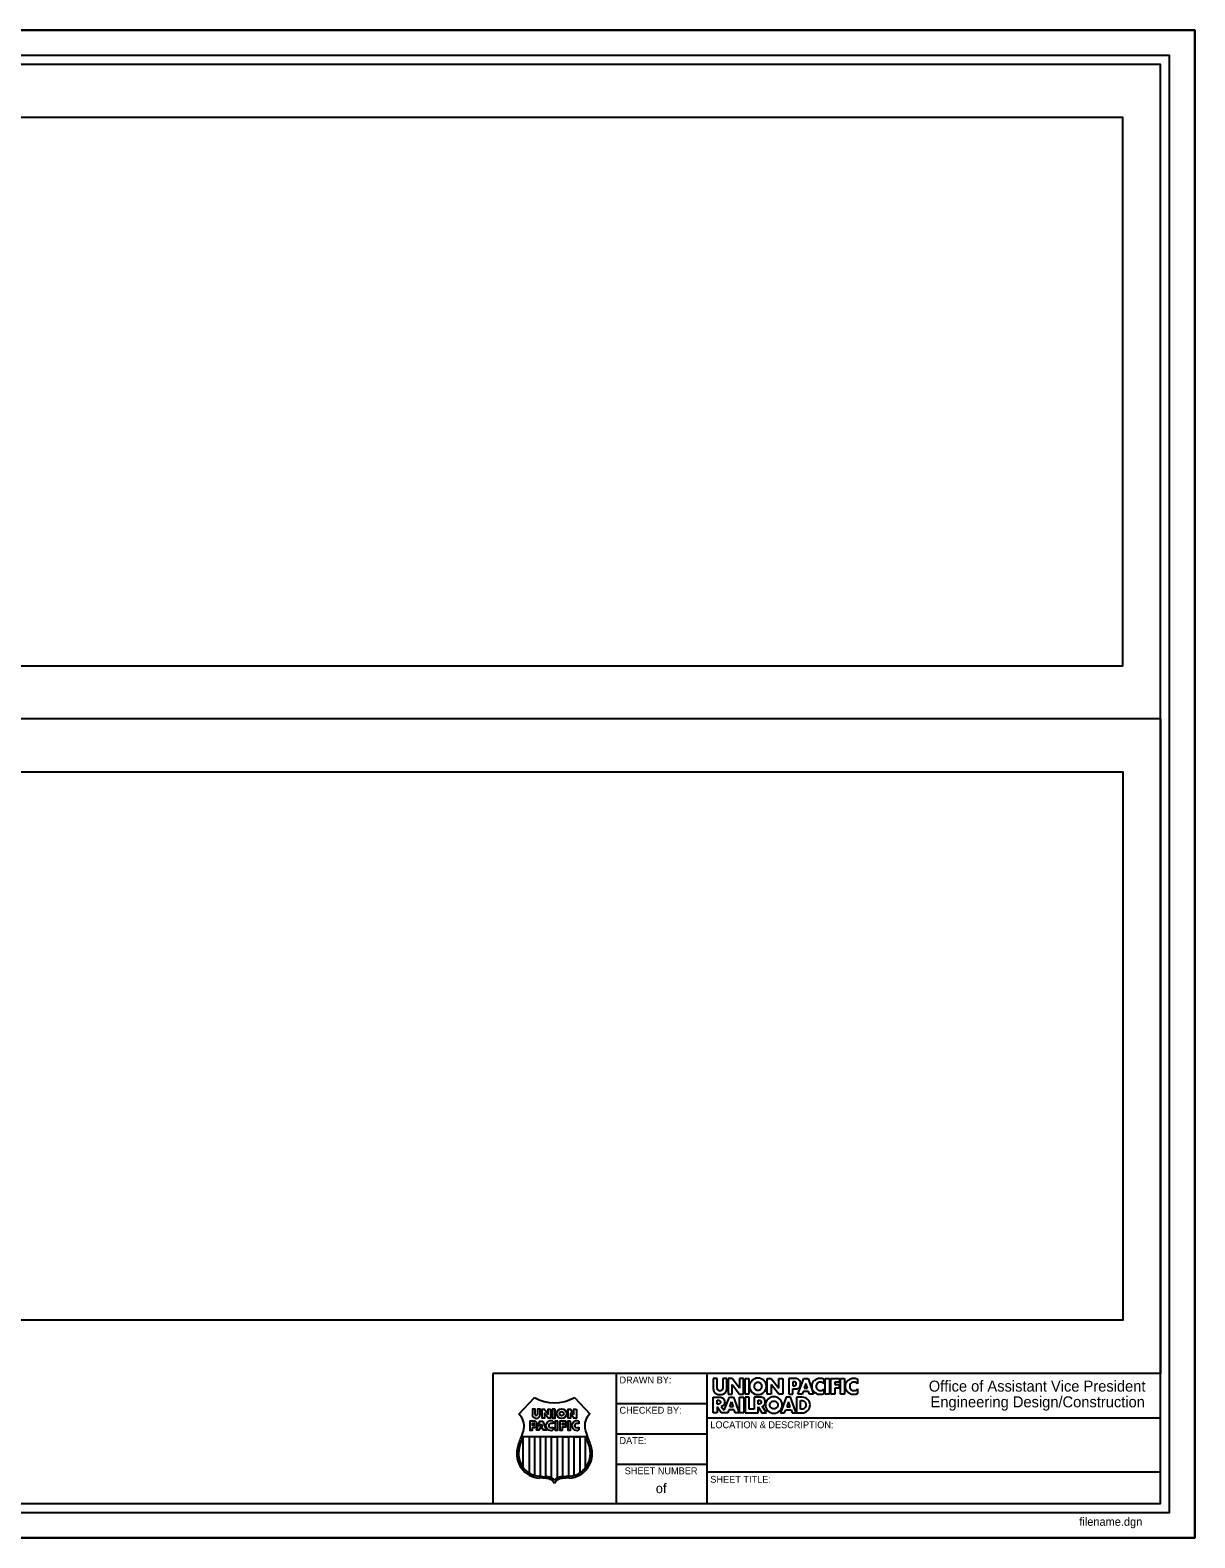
# Model space of a CAD drawing. Extents: x 0 to 17, y 0 to 11.
# Drawn here: x 8.5 to 17, y 0 to 11 of the extents above; entities that cross this region are included whole.
import ezdxf

# ---------------------------------------------------------------- set-up
doc = ezdxf.new("R2010")
doc.units = 0
for name, color, linetype in [('C-ANNO-NPLT', 7, 'Continuous'), ('Default', 7, 'Continuous'), ('G-ANNO-TTLB-TRIM', 7, 'Continuous'), ('G-BORDER', 7, 'Continuous')]:
    doc.layers.add(name, color=color, linetype=linetype)

msp = doc.modelspace()

# ---------------------------------------------------------------- linework, layer by layer
at = {"layer": 'C-ANNO-NPLT'}
for points in [[(0.975, 6.363), (16.475, 6.363), (16.475, 10.363), (0.975, 10.363)], [(0.975, 5.588), (16.475, 5.588), (16.475, 1.588), (0.975, 1.588)]]:
    msp.add_lwpolyline(points, close=True, dxfattribs=at)
at = {"layer": 'Default'}
for q in [(16.75, 10.75), (16.75, 1.2)]:
    msp.add_line((16.75, 5.975), q, dxfattribs=at)
at = {"layer": 'G-ANNO-TTLB-TRIM'}
msp.add_lwpolyline([(0, 0), (17, 0), (17, 11), (0, 11)], close=True, dxfattribs=at)
at = {"layer": 'G-BORDER'}
for p, q in [((16.75, 5.975), (0.7, 5.975)), ((16.75, 1.2), (11.876, 1.2)), ((11.876, 1.2), (11.876, 0.25)), ((12.776, 1.2), (12.776, 0.25)), ((13.439, 1.2), (13.439, 0.25)), ((13.515, 1.163), (13.485, 1.163)), ((13.485, 1.163), (13.485, 1.098)), ((13.515, 1.102), (13.515, 1.163)), ((13.584, 1.163), (13.555, 1.163)), ((13.555, 1.163), (13.555, 1.102)), ((13.584, 1.098), (13.584, 1.163)), ((13.623, 1.163), (13.593, 1.163)), ((13.593, 1.163), (13.593, 1.048)), ((13.677, 1.093), (13.623, 1.163)), ((13.623, 1.048), (13.623, 1.118)), ((13.623, 1.118), (13.623, 1.118)), ((13.623, 1.118), (13.677, 1.048)), ((13.707, 1.163), (13.677, 1.163)), ((13.677, 1.163), (13.677, 1.093)), ((13.707, 1.048), (13.707, 1.163)), ((13.717, 1.163), (13.746, 1.163)), ((13.717, 1.048), (13.717, 1.163)), ((13.746, 1.163), (13.746, 1.048)), ((13.879, 1.048), (13.879, 1.163)), ((13.879, 1.163), (13.909, 1.163)), ((13.909, 1.163), (13.963, 1.093)), ((13.963, 1.048), (13.909, 1.118)), ((13.909, 1.118), (13.909, 1.118)), ((13.909, 1.118), (13.909, 1.048)), ((13.963, 1.093), (13.963, 1.163)), ((13.963, 1.163), (13.993, 1.163)), ((13.993, 1.163), (13.993, 1.048)), ((14.081, 1.163), (14.036, 1.163)), ((14.036, 1.163), (14.036, 1.048)), ((14.07, 1.138), (14.065, 1.138)), ((14.065, 1.138), (14.065, 1.11)), ((14.065, 1.11), (14.07, 1.11)), ((14.103, 1.048), (14.146, 1.163)), ((14.146, 1.163), (14.177, 1.163)), ((14.161, 1.127), (14.149, 1.091)), ((14.173, 1.091), (14.161, 1.127)), ((14.177, 1.163), (14.218, 1.048)), ((14.293, 1.16), (14.293, 1.124)), ((14.303, 1.048), (14.303, 1.163)), ((14.303, 1.163), (14.333, 1.163)), ((14.333, 1.163), (14.333, 1.048)), ((14.343, 1.048), (14.343, 1.163)), ((14.343, 1.163), (14.407, 1.163)), ((14.407, 1.137), (14.373, 1.137)), ((14.373, 1.137), (14.373, 1.118)), ((14.373, 1.118), (14.403, 1.118)), ((14.403, 1.118), (14.403, 1.093)), ((14.407, 1.163), (14.407, 1.137)), ((14.413, 1.048), (14.413, 1.163)), ((14.413, 1.163), (14.443, 1.163)), ((14.443, 1.163), (14.443, 1.048)), ((14.537, 1.16), (14.537, 1.124)), ((12.066, 0.903), (12.18, 1.025)), ((12.18, 1.025), (12.18, 1.025)), ((12.472, 1.025), (12.586, 0.903)), ((13.485, 1.027), (13.53, 1.027)), ((13.485, 0.913), (13.485, 1.027)), ((13.515, 0.976), (13.515, 1.004)), ((13.515, 1.004), (13.518, 1.004)), ((13.566, 0.931), (13.603, 1.027)), ((13.593, 1.048), (13.623, 1.048)), ((13.603, 1.027), (13.633, 1.027)), ((13.606, 0.956), (13.618, 0.992)), ((13.618, 0.992), (13.63, 0.956)), ((13.633, 1.027), (13.674, 0.913)), ((13.677, 1.093), (13.677, 1.093)), ((13.677, 1.048), (13.707, 1.048)), ((13.678, 0.913), (13.678, 1.027)), ((13.678, 1.027), (13.708, 1.027)), ((13.708, 1.027), (13.708, 0.913)), ((13.746, 1.048), (13.717, 1.048)), ((13.718, 1.027), (13.718, 0.913)), ((13.747, 1.027), (13.718, 1.027)), ((13.747, 0.938), (13.747, 1.027)), ((13.828, 1.027), (13.784, 1.027)), ((13.784, 1.027), (13.784, 0.938)), ((13.813, 0.976), (13.813, 1.004)), ((13.813, 1.004), (13.816, 1.004)), ((13.909, 1.048), (13.879, 1.048)), ((13.963, 1.093), (13.963, 1.093)), ((13.993, 1.048), (13.963, 1.048)), ((14.018, 1.027), (13.976, 0.913)), ((14.05, 1.027), (14.018, 1.027)), ((14.034, 0.992), (14.022, 0.955)), ((14.046, 0.955), (14.034, 0.992)), ((14.036, 1.048), (14.065, 1.048)), ((14.091, 0.913), (14.05, 1.027)), ((14.065, 1.086), (14.082, 1.086)), ((14.065, 1.048), (14.065, 1.086)), ((14.135, 1.027), (14.093, 1.027)), ((14.093, 1.027), (14.093, 0.913)), ((14.133, 1.048), (14.103, 1.048)), ((14.122, 0.938), (14.122, 1.002)), ((14.122, 1.002), (14.129, 1.002)), ((14.141, 1.068), (14.133, 1.048)), ((14.181, 1.068), (14.141, 1.068)), ((14.149, 1.091), (14.173, 1.091)), ((14.188, 1.048), (14.181, 1.068)), ((14.218, 1.048), (14.188, 1.048)), ((14.293, 1.086), (14.293, 1.051)), ((14.333, 1.048), (14.303, 1.048)), ((14.373, 1.048), (14.343, 1.048)), ((14.403, 1.093), (14.373, 1.093)), ((14.373, 1.093), (14.373, 1.048)), ((14.443, 1.048), (14.413, 1.048)), ((14.537, 1.086), (14.537, 1.051)), ((12.776, 0.979), (13.439, 0.979)), ((13.515, 0.913), (13.485, 0.913)), ((13.518, 0.976), (13.515, 0.976)), ((13.543, 0.913), (13.515, 0.956)), ((13.515, 0.956), (13.515, 0.913)), ((13.591, 0.913), (13.543, 0.913)), ((13.544, 0.959), (13.566, 0.931)), ((13.598, 0.933), (13.591, 0.913)), ((13.637, 0.933), (13.598, 0.933)), ((13.63, 0.956), (13.606, 0.956)), ((13.644, 0.913), (13.637, 0.933)), ((13.674, 0.913), (13.644, 0.913)), ((13.708, 0.913), (13.678, 0.913)), ((13.718, 0.913), (13.813, 0.913)), ((13.784, 0.938), (13.747, 0.938)), ((13.816, 0.976), (13.813, 0.976)), ((13.813, 0.913), (13.813, 0.956)), ((13.813, 0.956), (13.839, 0.913)), ((13.839, 0.913), (13.875, 0.913)), ((13.875, 0.913), (13.843, 0.96)), ((13.976, 0.913), (14.006, 0.913)), ((14.006, 0.913), (14.014, 0.933)), ((14.014, 0.933), (14.053, 0.933)), ((14.022, 0.955), (14.046, 0.955)), ((14.053, 0.933), (14.061, 0.913)), ((14.061, 0.913), (14.091, 0.913)), ((14.093, 0.913), (14.135, 0.913)), ((14.129, 0.938), (14.122, 0.938)), ((12.217, 0.797), (12.213, 0.786)), ((12.316, 0.851), (12.316, 0.831)), ((12.316, 0.807), (12.316, 0.787)), ((12.505, 0.851), (12.505, 0.831)), ((12.505, 0.807), (12.505, 0.787)), ((13.439, 0.875), (16.75, 0.875)), ((12.567, 0.738), (12.085, 0.738)), ((12.085, 0.738), (12.098, 0.738)), ((12.098, 0.738), (12.096, 0.733)), ((12.556, 0.733), (12.554, 0.738)), ((12.554, 0.738), (12.554, 0.738)), ((12.554, 0.738), (12.556, 0.733)), ((12.554, 0.738), (12.567, 0.738)), ((12.556, 0.733), (12.554, 0.738)), ((12.554, 0.738), (12.554, 0.738)), ((12.776, 0.758), (13.439, 0.758)), ((12.214, 0.45), (12.27, 0.446)), ((12.382, 0.446), (12.438, 0.45)), ((12.776, 0.538), (13.439, 0.538)), ((13.439, 0.482), (16.75, 0.482)), ((12.269, 0.433), (12.216, 0.437)), ((12.436, 0.437), (12.383, 0.433))]:
    msp.add_line(p, q, dxfattribs=at)
for points in [[(0, 11), (17, 11), (17, 0), (0, 0)], [(0.165, 0.185), (16.815, 0.185), (16.815, 10.815), (0.165, 10.815)], [(0.7, 0.25), (16.75, 0.25), (16.75, 10.75), (0.7, 10.75)], [(12.297, 0.94), (12.297, 0.873), (12.28, 0.873), (12.254, 0.909), (12.254, 0.873), (12.236, 0.873), (12.236, 0.94), (12.254, 0.94), (12.28, 0.903), (12.28, 0.94)], [(12.332, 0.94), (12.312, 0.94), (12.312, 0.873), (12.332, 0.873)], [(12.487, 0.94), (12.487, 0.873), (12.469, 0.873), (12.444, 0.909), (12.444, 0.873), (12.426, 0.873), (12.426, 0.94), (12.444, 0.94), (12.469, 0.903), (12.469, 0.94)], [(12.241, 0.852), (12.265, 0.786), (12.246, 0.786), (12.242, 0.797), (12.217, 0.797), (12.213, 0.786), (12.195, 0.786), (12.219, 0.852)], [(12.23, 0.832), (12.237, 0.813), (12.223, 0.813)], [(12.351, 0.852), (12.331, 0.852), (12.331, 0.786), (12.351, 0.786)], [(12.412, 0.852), (12.366, 0.852), (12.366, 0.786), (12.385, 0.786), (12.385, 0.809), (12.412, 0.809), (12.412, 0.824), (12.385, 0.824), (12.385, 0.837), (12.412, 0.837)], [(12.444, 0.852), (12.424, 0.852), (12.424, 0.786), (12.444, 0.786)], [(12.264, 0.446), (12.264, 0.738), (12.223, 0.738), (12.223, 0.449)], [(12.388, 0.446), (12.388, 0.738), (12.429, 0.738), (12.429, 0.449)]]:
    msp.add_lwpolyline(points, close=True, dxfattribs=at)
for points in [[(13.535, 1.071), (13.528, 1.072), (13.523, 1.074), (13.52, 1.077), (13.517, 1.081), (13.516, 1.086), (13.515, 1.091), (13.515, 1.097), (13.515, 1.102)], [(13.555, 1.102), (13.555, 1.097), (13.554, 1.091), (13.553, 1.086), (13.552, 1.081), (13.549, 1.077), (13.546, 1.074), (13.541, 1.072), (13.535, 1.071)], [(13.812, 1.166), (13.799, 1.165), (13.788, 1.161), (13.777, 1.156), (13.768, 1.148), (13.761, 1.139), (13.755, 1.129), (13.751, 1.118), (13.75, 1.105)], [(13.75, 1.105), (13.751, 1.093), (13.755, 1.082), (13.761, 1.071), (13.768, 1.062), (13.777, 1.055), (13.788, 1.049), (13.799, 1.046), (13.812, 1.045)], [(13.812, 1.134), (13.806, 1.133), (13.801, 1.131), (13.796, 1.129), (13.791, 1.126), (13.788, 1.121), (13.785, 1.116), (13.783, 1.111), (13.783, 1.105)], [(13.783, 1.105), (13.783, 1.099), (13.785, 1.094), (13.788, 1.089), (13.791, 1.085), (13.796, 1.081), (13.801, 1.079), (13.806, 1.077), (13.812, 1.077)], [(13.873, 1.105), (13.872, 1.118), (13.868, 1.129), (13.862, 1.139), (13.855, 1.148), (13.846, 1.156), (13.836, 1.161), (13.824, 1.165), (13.812, 1.166)], [(13.841, 1.105), (13.84, 1.111), (13.839, 1.116), (13.836, 1.121), (13.832, 1.126), (13.828, 1.129), (13.823, 1.131), (13.818, 1.133), (13.812, 1.134)], [(13.812, 1.045), (13.824, 1.046), (13.836, 1.049), (13.846, 1.055), (13.855, 1.062), (13.862, 1.071), (13.868, 1.082), (13.872, 1.093), (13.873, 1.105)], [(13.812, 1.077), (13.818, 1.077), (13.823, 1.079), (13.828, 1.081), (13.832, 1.085), (13.836, 1.089), (13.839, 1.094), (13.84, 1.099), (13.841, 1.105)], [(14.091, 1.124), (14.091, 1.129), (14.09, 1.132), (14.088, 1.135), (14.085, 1.137), (14.082, 1.137), (14.078, 1.138), (14.074, 1.138), (14.07, 1.138)], [(14.07, 1.11), (14.074, 1.11), (14.078, 1.11), (14.081, 1.111), (14.085, 1.112), (14.087, 1.113), (14.09, 1.116), (14.091, 1.119), (14.091, 1.124)], [(14.122, 1.125), (14.121, 1.134), (14.119, 1.142), (14.116, 1.148), (14.111, 1.153), (14.105, 1.157), (14.098, 1.16), (14.09, 1.162), (14.081, 1.163)], [(14.082, 1.086), (14.091, 1.086), (14.099, 1.088), (14.106, 1.091), (14.112, 1.095), (14.116, 1.1), (14.12, 1.107), (14.121, 1.115), (14.122, 1.125)], [(14.206, 1.105), (14.206, 1.111), (14.207, 1.116), (14.208, 1.122), (14.21, 1.128), (14.212, 1.133), (14.215, 1.138), (14.218, 1.142), (14.223, 1.147)], [(14.224, 1.062), (14.22, 1.067), (14.216, 1.071), (14.213, 1.076), (14.21, 1.081), (14.208, 1.087), (14.207, 1.093), (14.206, 1.099), (14.206, 1.105)], [(14.223, 1.147), (14.227, 1.151), (14.232, 1.154), (14.237, 1.158), (14.242, 1.16), (14.248, 1.163), (14.254, 1.164), (14.26, 1.165), (14.266, 1.165)], [(14.267, 1.137), (14.26, 1.136), (14.254, 1.134), (14.249, 1.131), (14.245, 1.127), (14.241, 1.123), (14.239, 1.117), (14.237, 1.111), (14.237, 1.105)], [(14.237, 1.105), (14.237, 1.099), (14.239, 1.093), (14.241, 1.087), (14.245, 1.083), (14.249, 1.079), (14.255, 1.076), (14.261, 1.074), (14.268, 1.074)], [(14.266, 1.165), (14.27, 1.165), (14.273, 1.165), (14.276, 1.164), (14.28, 1.164), (14.283, 1.163), (14.286, 1.162), (14.29, 1.161), (14.293, 1.16)], [(14.293, 1.124), (14.291, 1.127), (14.288, 1.129), (14.285, 1.131), (14.281, 1.133), (14.278, 1.135), (14.275, 1.136), (14.271, 1.137), (14.267, 1.137)], [(14.45, 1.105), (14.45, 1.111), (14.451, 1.116), (14.452, 1.122), (14.454, 1.128), (14.457, 1.133), (14.459, 1.138), (14.463, 1.142), (14.467, 1.147)], [(14.468, 1.062), (14.464, 1.067), (14.46, 1.071), (14.457, 1.076), (14.455, 1.081), (14.452, 1.087), (14.451, 1.093), (14.45, 1.099), (14.45, 1.105)], [(14.467, 1.147), (14.471, 1.151), (14.476, 1.154), (14.481, 1.158), (14.487, 1.16), (14.493, 1.163), (14.498, 1.164), (14.504, 1.165), (14.51, 1.165)], [(14.511, 1.137), (14.505, 1.136), (14.499, 1.134), (14.494, 1.131), (14.489, 1.127), (14.486, 1.123), (14.483, 1.117), (14.481, 1.111), (14.481, 1.105)], [(14.481, 1.105), (14.481, 1.099), (14.483, 1.093), (14.486, 1.087), (14.489, 1.083), (14.494, 1.079), (14.499, 1.076), (14.505, 1.074), (14.512, 1.074)], [(14.51, 1.165), (14.514, 1.165), (14.517, 1.165), (14.521, 1.164), (14.524, 1.164), (14.527, 1.163), (14.531, 1.162), (14.534, 1.161), (14.537, 1.16)], [(14.537, 1.124), (14.535, 1.127), (14.532, 1.129), (14.529, 1.131), (14.526, 1.133), (14.522, 1.135), (14.519, 1.136), (14.515, 1.137), (14.511, 1.137)], [(13.485, 1.098), (13.485, 1.093), (13.485, 1.087), (13.486, 1.082), (13.487, 1.077), (13.488, 1.072), (13.49, 1.067), (13.493, 1.062), (13.497, 1.058)], [(13.497, 1.058), (13.501, 1.055), (13.505, 1.052), (13.51, 1.05), (13.514, 1.048), (13.519, 1.047), (13.524, 1.046), (13.53, 1.045), (13.535, 1.045)], [(13.518, 1.004), (13.521, 1.004), (13.525, 1.004), (13.528, 1.003), (13.531, 1.002), (13.534, 1), (13.536, 0.997), (13.538, 0.994), (13.538, 0.99)], [(13.53, 1.027), (13.538, 1.026), (13.545, 1.025), (13.552, 1.022), (13.558, 1.018), (13.563, 1.013), (13.566, 1.007), (13.568, 1), (13.569, 0.992)], [(13.535, 1.045), (13.54, 1.045), (13.545, 1.046), (13.55, 1.047), (13.555, 1.048), (13.56, 1.05), (13.564, 1.052), (13.568, 1.055), (13.573, 1.058)], [(13.569, 0.992), (13.568, 0.986), (13.567, 0.98), (13.565, 0.975), (13.563, 0.971), (13.559, 0.966), (13.555, 0.963), (13.55, 0.961), (13.544, 0.959)], [(13.573, 1.058), (13.576, 1.062), (13.579, 1.067), (13.581, 1.072), (13.583, 1.077), (13.584, 1.082), (13.584, 1.087), (13.584, 1.093), (13.584, 1.098)], [(13.816, 1.004), (13.82, 1.004), (13.823, 1.004), (13.826, 1.003), (13.829, 1.002), (13.832, 1), (13.833, 0.997), (13.834, 0.994), (13.835, 0.99)], [(13.835, 0.99), (13.834, 0.986), (13.833, 0.982), (13.832, 0.98), (13.829, 0.978), (13.826, 0.977), (13.823, 0.976), (13.82, 0.976), (13.816, 0.976)], [(13.865, 0.992), (13.864, 1), (13.862, 1.007), (13.859, 1.013), (13.855, 1.018), (13.85, 1.022), (13.843, 1.025), (13.836, 1.026), (13.828, 1.027)], [(13.843, 0.96), (13.848, 0.961), (13.853, 0.963), (13.857, 0.967), (13.86, 0.971), (13.862, 0.975), (13.864, 0.98), (13.865, 0.986), (13.865, 0.992)], [(13.928, 1.03), (13.915, 1.029), (13.903, 1.025), (13.893, 1.02), (13.884, 1.013), (13.877, 1.004), (13.871, 0.993), (13.867, 0.982), (13.866, 0.97)], [(13.898, 0.97), (13.899, 0.976), (13.901, 0.981), (13.903, 0.986), (13.907, 0.99), (13.911, 0.993), (13.916, 0.996), (13.922, 0.998), (13.928, 0.998)], [(13.989, 0.97), (13.988, 0.982), (13.984, 0.993), (13.978, 1.004), (13.971, 1.013), (13.962, 1.02), (13.951, 1.025), (13.94, 1.029), (13.928, 1.03)], [(13.928, 0.998), (13.933, 0.998), (13.939, 0.996), (13.944, 0.993), (13.948, 0.99), (13.951, 0.986), (13.954, 0.981), (13.956, 0.976), (13.957, 0.97)], [(14.129, 1.002), (14.136, 1.001), (14.142, 0.999), (14.148, 0.997), (14.153, 0.993), (14.157, 0.988), (14.159, 0.983), (14.161, 0.977), (14.162, 0.97)], [(14.193, 0.97), (14.191, 0.981), (14.188, 0.992), (14.183, 1.002), (14.175, 1.01), (14.167, 1.017), (14.157, 1.022), (14.146, 1.025), (14.135, 1.027)], [(14.267, 1.045), (14.261, 1.045), (14.255, 1.046), (14.249, 1.047), (14.244, 1.049), (14.238, 1.052), (14.233, 1.055), (14.228, 1.058), (14.224, 1.062)], [(14.293, 1.051), (14.289, 1.049), (14.286, 1.048), (14.283, 1.047), (14.28, 1.046), (14.276, 1.046), (14.273, 1.046), (14.27, 1.045), (14.267, 1.045)], [(14.268, 1.074), (14.271, 1.074), (14.275, 1.075), (14.278, 1.076), (14.282, 1.077), (14.285, 1.079), (14.288, 1.081), (14.291, 1.083), (14.293, 1.086)], [(14.511, 1.045), (14.505, 1.045), (14.499, 1.046), (14.494, 1.047), (14.488, 1.049), (14.483, 1.052), (14.478, 1.055), (14.473, 1.058), (14.468, 1.062)], [(14.537, 1.051), (14.534, 1.049), (14.531, 1.048), (14.527, 1.047), (14.524, 1.046), (14.521, 1.046), (14.518, 1.046), (14.515, 1.045), (14.511, 1.045)], [(14.512, 1.074), (14.515, 1.074), (14.519, 1.075), (14.522, 1.076), (14.526, 1.077), (14.529, 1.079), (14.532, 1.081), (14.535, 1.083), (14.537, 1.086)], [(12.185, 0.9), (12.185, 0.94), (12.165, 0.94), (12.165, 0.9)], [(12.222, 0.9), (12.222, 0.94), (12.202, 0.94), (12.202, 0.9)], [(13.538, 0.99), (13.538, 0.985), (13.536, 0.982), (13.534, 0.98), (13.531, 0.978), (13.528, 0.977), (13.525, 0.976), (13.521, 0.976), (13.518, 0.976)], [(13.866, 0.97), (13.867, 0.957), (13.871, 0.946), (13.877, 0.936), (13.884, 0.927), (13.893, 0.919), (13.903, 0.914), (13.915, 0.91), (13.928, 0.909)], [(13.928, 0.941), (13.922, 0.941), (13.916, 0.943), (13.911, 0.946), (13.907, 0.949), (13.903, 0.954), (13.901, 0.959), (13.899, 0.964), (13.898, 0.97)], [(13.928, 0.909), (13.94, 0.91), (13.951, 0.914), (13.962, 0.919), (13.971, 0.927), (13.978, 0.936), (13.984, 0.946), (13.988, 0.957), (13.989, 0.97)], [(13.957, 0.97), (13.956, 0.964), (13.954, 0.959), (13.951, 0.954), (13.948, 0.949), (13.944, 0.946), (13.939, 0.943), (13.933, 0.941), (13.928, 0.941)], [(14.162, 0.97), (14.161, 0.962), (14.159, 0.955), (14.156, 0.95), (14.152, 0.945), (14.147, 0.942), (14.142, 0.939), (14.135, 0.938), (14.129, 0.938)], [(14.135, 0.913), (14.146, 0.913), (14.157, 0.917), (14.167, 0.922), (14.175, 0.929), (14.183, 0.937), (14.188, 0.947), (14.191, 0.958), (14.193, 0.97)], [(12.176, 0.852), (12.147, 0.852), (12.147, 0.786), (12.165, 0.786), (12.165, 0.804), (12.176, 0.804)], [(12.175, 0.82), (12.165, 0.82), (12.165, 0.837), (12.175, 0.837)], [(12.099, 0.511), (12.099, 0.738), (12.098, 0.738)], [(12.182, 0.456), (12.182, 0.738), (12.141, 0.738), (12.141, 0.474)], [(12.305, 0.436), (12.305, 0.738), (12.347, 0.738), (12.347, 0.436)], [(12.47, 0.456), (12.47, 0.738), (12.512, 0.738), (12.512, 0.474)], [(12.553, 0.511), (12.553, 0.738), (12.554, 0.738)]]:
    msp.add_lwpolyline(points, dxfattribs=at)
for radius in [0.0354, 0.0156]:
    msp.add_circle((12.379, 0.906), radius, dxfattribs=at)
for centre, radius, start, end in [((12.326, 1.28), 0.294, 240.2188, 299.7811), ((11.988, 0.817), 0.117, 348.9687, 47.9012), ((12.193, 0.9), 0.0282, 180, 0), ((12.193, 0.9), 0.00844, 180, 0), ((12.664, 0.817), 0.117, 132.0988, 191.0313), ((11.839, 0.849), 0.27, 335.725, 348.2065), ((12.175, 0.828), 0.00844, 270, 90), ((12.176, 0.828), 0.024, 270, 90), ((12.3, 0.819), 0.0354, 63.8727, 296.1273), ((12.3, 0.819), 0.0156, 90, 270), ((12.3, 0.799), 0.0354, 63.8727, 90), ((12.3, 0.839), 0.0354, 270, 296.1273), ((12.489, 0.819), 0.0354, 63.8727, 296.1273), ((12.489, 0.819), 0.0156, 90, 270), ((12.489, 0.799), 0.0354, 63.8727, 90), ((12.489, 0.839), 0.0354, 270, 296.1273), ((12.814, 0.849), 0.27, 191.7935, 204.275), ((12.537, 0.536), 0.496, 155.9477, 166.1116), ((12.537, 0.536), 0.484, 155.2938, 165.9327), ((12.537, 0.536), 0.484, 155.9477, 165.9327), ((12.115, 0.536), 0.484, 14.0673, 24.0523), ((12.115, 0.536), 0.484, 14.0673, 24.0523), ((12.115, 0.536), 0.484, 14.0673, 24.0523), ((12.115, 0.536), 0.496, 13.8884, 24.0523), ((12.228, 0.613), 0.177, 166.2761, 266.1574), ((12.228, 0.613), 0.164, 165.7618, 218.6873), ((12.228, 0.613), 0.164, 165.7618, 265.3226), ((12.425, 0.613), 0.177, 273.8426, 13.7239), ((12.425, 0.613), 0.164, 274.6774, 14.2382), ((12.425, 0.613), 0.164, 321.3127, 14.2382), ((12.228, 0.613), 0.164, 238.0229, 253.8238), ((12.258, 0.333), 0.114, 62.6569, 84.0072), ((12.394, 0.333), 0.114, 95.9928, 117.3431), ((12.425, 0.613), 0.164, 286.1762, 301.9771), ((12.258, 0.333), 0.101, 63.0959, 83.8953), ((12.265, 0.368), 0.0675, 25.7451, 54.9835), ((12.258, 0.333), 0.114, 62.6569, 65.4029), ((12.265, 0.368), 0.0798, 40.3951, 55.6137), ((12.265, 0.368), 0.0798, 40.3951, 55.6137), ((12.265, 0.368), 0.0798, 40.3951, 55.6137), ((12.387, 0.368), 0.0798, 124.3863, 139.6049), ((12.387, 0.368), 0.0798, 124.3863, 139.6049), ((12.387, 0.368), 0.0798, 124.3863, 139.6049), ((12.387, 0.368), 0.0675, 125.0165, 154.2549), ((12.394, 0.333), 0.114, 114.5967, 117.3431), ((12.394, 0.333), 0.101, 96.1047, 116.9041)]:
    msp.add_arc(centre, radius, start, end, dxfattribs=at)

# ---------------------------------------------------------------- texts
for s, height, p in [('DRAWN BY:  ', 0.05, (12.801, 1.127)), ('Office of Assistant Vice President', 0.08, (15.058, 1.067)), ('Engineering Design/Construction', 0.08, (15.071, 0.952)), ('CHECKED BY:  ', 0.05, (12.801, 0.906)), ('LOCATION & DESCRIPTION:', 0.05, (13.464, 0.8)), ('DATE:', 0.05, (12.801, 0.685)), ('SHEET NUMBER', 0.05, (12.839, 0.464)), ('SHEET TITLE:', 0.05, (13.464, 0.402))]:
    msp.add_text(s, height=height, rotation=0.004, dxfattribs=at).set_placement(p)
for s, height, p in [('of', 0.07, (13.066, 0.326)), ('filename.dgn', 0.06, (16.157, 0.088))]:
    msp.add_text(s, height=height, dxfattribs=at).set_placement(p)

doc.saveas('drawing.dxf')
